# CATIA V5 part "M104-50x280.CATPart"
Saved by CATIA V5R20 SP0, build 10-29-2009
Part number: M104-50x280
Source: Unknown
Bounding box of the stored display mesh (mm): x -24.865 to 24.865, y -24.997 to 24.997, z 0 to 280
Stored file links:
  C:\Users\Utente\Desktop\IO LAVORO\3D X SITO CF\X SITO\M104\M104-50x280.CATPart
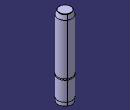
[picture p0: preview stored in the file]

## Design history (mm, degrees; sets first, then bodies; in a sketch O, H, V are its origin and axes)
Body1 (main body)
  Solid1 "PartBody": solid without history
